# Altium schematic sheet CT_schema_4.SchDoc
size 294 x 134 mm
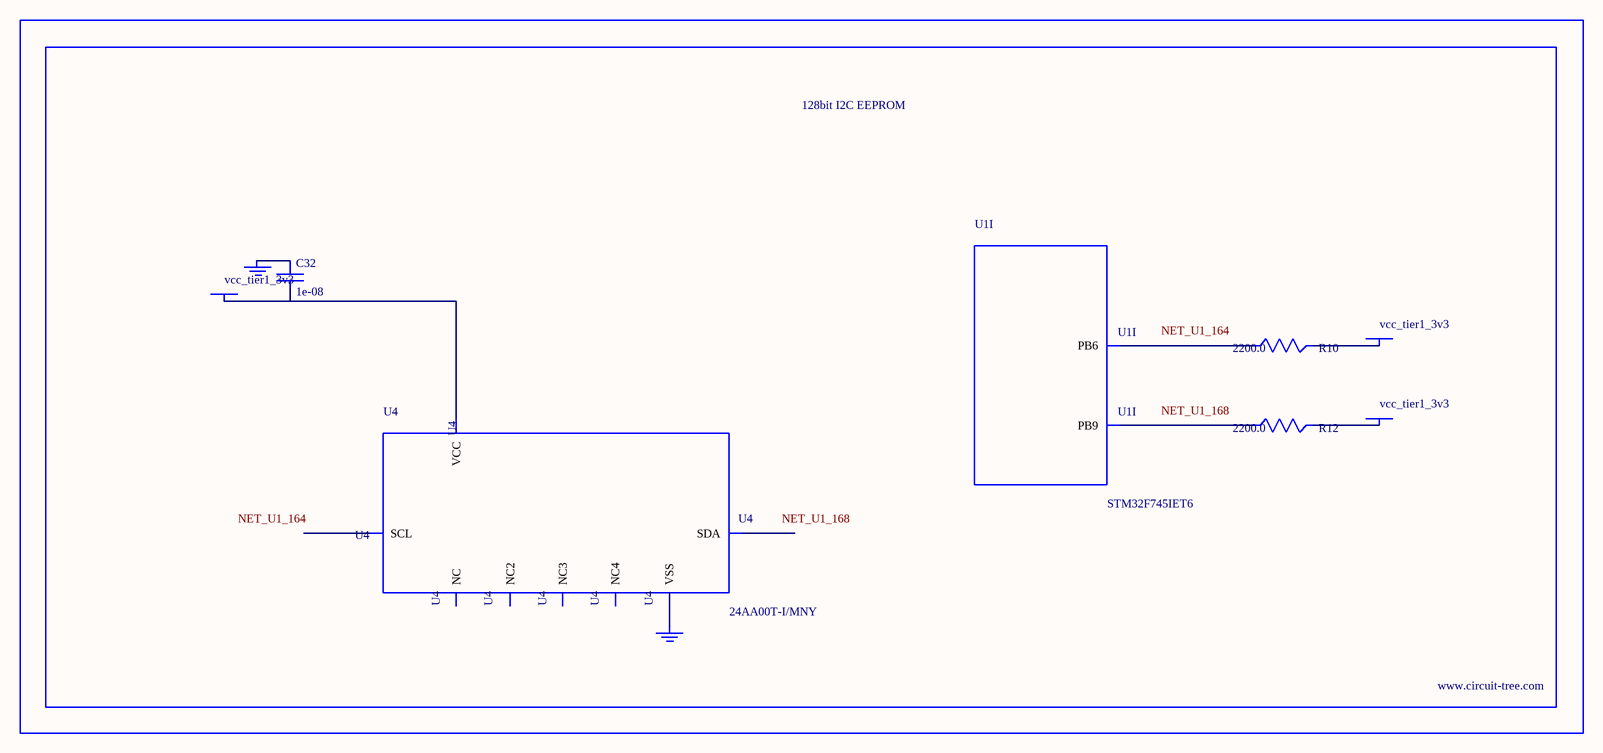
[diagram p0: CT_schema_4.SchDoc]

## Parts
BORDER3  (no value)
C32  1e-08  [C0402]
GND_INSTANCE_3_0  (no value)
GND_INSTANCE_3_1  (no value)
POWER_INSTANCE_3_0  vcc_tier1_3v3
POWER_INSTANCE_3_1  vcc_tier1_3v3
POWER_INSTANCE_3_2  vcc_tier1_3v3
R10  2200.0  [R0603]
R12  2200.0  [R0603]
U1  STM32F745IET6  [LQFP176]  (part I of 14)
U4  24AA00T-I/MNY  [TDFN-8/6MM]

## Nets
NetC32_1: C32.1 GND_INSTANCE_3_0.0(GND)
NetC32_2: C32.2 POWER_INSTANCE_3_0.0(PWR) U4.8(VCC)
NetGND_INSTANCE_3_1_0: GND_INSTANCE_3_1.0(GND) U4.4(VSS)
NetPOWER_INSTANCE_3_1_0: POWER_INSTANCE_3_1.0(PWR) R10.2
NetPOWER_INSTANCE_3_2_0: POWER_INSTANCE_3_2.0(PWR) R12.2
NetR10_1: R10.1 U1.164(PB6)
NetR12_1: R12.1 U1.168(PB9)

Not connected (* = marked no-connect by the designer): U4 1(NC) 2(NC2) 3(NC3) 5(SDA) 6(SCL) 7(NC4)

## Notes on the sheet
- Labels drawn without touching a wire or pin: NET_U1_164, NET_U1_168

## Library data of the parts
BORDER3 = BORDER_PAGE3
C32 = C0402C103K3RAC
GND_INSTANCE_3_0 GND_INSTANCE_3_1 = GND
POWER_INSTANCE_3_0-POWER_INSTANCE_3_2 = PWR
R10 R12 = RC0603JR-072K2L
